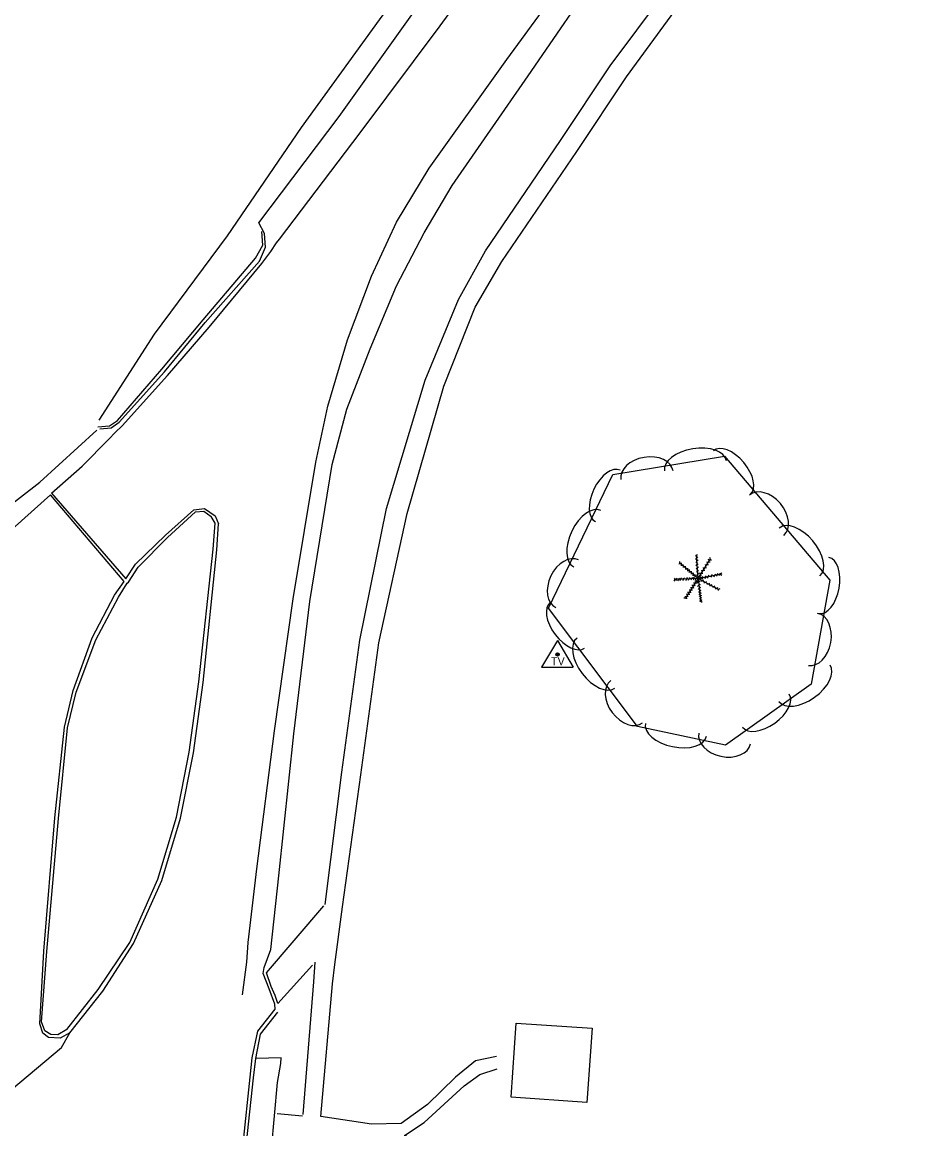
# Model space of a CAD drawing. Extents: x 1042086 to 1119166, y 1916606 to 1927565.
# Drawn here: x 1043276.4 to 1043446.1, y 1926644.3 to 1926851.6 of the extents above; entities that cross this region are included whole.
import ezdxf

# ---------------------------------------------------------------- set-up
doc = ezdxf.new("R2010")
doc.units = 0
for name, color, linetype in [('S_BUILDING', 7, 'Continuous'), ('S_CURB', 7, 'Continuous'), ('S_EDGE_CONCRETE', 7, 'Continuous'), ('S_EDGE_PAVEMENT', 7, 'Continuous'), ('S_GRAVEL_ROAD', 7, 'Continuous'), ('S_SECONDARY_CTL', 7, 'Continuous'), ('S_SHOULDER', 7, 'Continuous'), ('S_SIDEWALK', 7, 'Continuous'), ('S_TREE', 7, 'Continuous')]:
    doc.layers.add(name, color=color, linetype=linetype)

msp = doc.modelspace()

# ---------------------------------------------------------------- linework, layer by layer
at = {"layer": 'S_BUILDING'}
msp.add_lwpolyline([(1043382.17, 1926649.21), (1043367.97, 1926650.21), (1043368.94, 1926664.09), (1043383.15, 1926663.1)], close=True, dxfattribs=at)
at = {"layer": 'S_CURB'}
for points in [[(1043290.59, 1926775.81), (1043292.73, 1926775.98), (1043294.25, 1926776.99), (1043302.57, 1926786.62), (1043310.27, 1926795.81), (1043320.09, 1926807.37), (1043321.47, 1926809.84), (1043321.31, 1926812.39)], [(1043296.32, 1926746.71), (1043298.1, 1926749.51), (1043303.62, 1926755.08), (1043308.84, 1926759.86), (1043310.42, 1926759.98), (1043311.82, 1926759.01)], [(1043284.75, 1926662.87), (1043290.65, 1926670.35), (1043296.54, 1926679.18), (1043301.78, 1926691.03), (1043305.32, 1926702.69), (1043307.65, 1926714.83), (1043309.46, 1926728.01), (1043312.18, 1926752.86), (1043312.55, 1926757.72), (1043311.82, 1926759.01)], [(1043284.75, 1926662.87), (1043283.09, 1926661.87), (1043281.76, 1926661.95), (1043280.61, 1926662.63), (1043279.99, 1926664.31), (1043280.99, 1926677.5), (1043283.18, 1926702.42), (1043284.88, 1926719.42), (1043286.53, 1926726.07), (1043290.21, 1926735.89), (1043294.45, 1926743.85), (1043296.09, 1926746.5), (1043296.32, 1926746.71)], [(1043203.91, 1926532.06), (1043222.97, 1926548.25), (1043242.02, 1926564.43), (1043261.02, 1926580.68), (1043280.9, 1926597.45), (1043299.84, 1926613.77), (1043313.23, 1926625.02), (1043315.83, 1926627.5), (1043317.07, 1926628.88), (1043319.73, 1926653.81), (1043320.19, 1926657.43), (1043321.03, 1926661.98), (1043324.28, 1926666.15)]]:
    msp.add_lwpolyline(points, dxfattribs=at)
at = {"layer": 'S_EDGE_CONCRETE'}
for points in [[(1043333.14, 1926686.28), (1043336.25, 1926711.07), (1043339.64, 1926735.81), (1043344.67, 1926760.46), (1043351.86, 1926784.55), (1043358.12, 1926799.66), (1043363.22, 1926808.77), (1043377.25, 1926829.45), (1043386.53, 1926843.44), (1043401.54, 1926863.54), (1043417.33, 1926882.95), (1043432.92, 1926902.49), (1043449.21, 1926921.54), (1043465.95, 1926940.19), (1043482.96, 1926958.51), (1043500.59, 1926976.22), (1043518.59, 1926993.74), (1043537.15, 1927010.47), (1043556.08, 1927026.84), (1043574.87, 1927043.32), (1043593.74, 1927059.7), (1043596.5, 1927062.22)], [(1043332.36, 1926646.56), (1043334.5, 1926671.41), (1043334.97, 1926675.06), (1043336.37, 1926685.87), (1043339.84, 1926710.61), (1043343.21, 1926735.35), (1043348.53, 1926759.57), (1043355.39, 1926783.41), (1043361.24, 1926798.22), (1043366.25, 1926806.77), (1043380.3, 1926827.37), (1043389.58, 1926841.36), (1043404.26, 1926861.45)], [(1042911.59, 1926420.57), (1042897.9, 1926435.96), (1042900.77, 1926438.95), (1042919.78, 1926455.34), (1042939.53, 1926471.89), (1042958.48, 1926488.19), (1042977.65, 1926504.25), (1042996.58, 1926520.57), (1043015.53, 1926536.87), (1043034.78, 1926552.83), (1043053.68, 1926569.19), (1043072.77, 1926585.33), (1043091.84, 1926601.49), (1043110.9, 1926617.67), (1043129.98, 1926633.83), (1043149.08, 1926649.95), (1043168.09, 1926666.19), (1043187.12, 1926682.4), (1043206.26, 1926698.48), (1043225.26, 1926714.73), (1043244.49, 1926730.7), (1043263.56, 1926746.87), (1043281.72, 1926763.08)], [(1043285.33, 1926662.23), (1043283.52, 1926661.24), (1043281.31, 1926661.4), (1043280.27, 1926662.21), (1043279.69, 1926663.94), (1043280.44, 1926677.57), (1043282.5, 1926702.51), (1043284.34, 1926719.5), (1043285.93, 1926726.4), (1043289.5, 1926736.28), (1043293.67, 1926744.28), (1043295.47, 1926746.84), (1043281.72, 1926763.08)], [(1043322.19, 1926673.51), (1043332.89, 1926686.06)], [(1043324.26, 1926667.74), (1043330.77, 1926674.94)], [(1043329, 1926646.95), (1043331.06, 1926671.81), (1043331.29, 1926675.48)], [(1043324.26, 1926667.74), (1043323.76, 1926669.26), (1043323.01, 1926670.95), (1043322.19, 1926673.51)]]:
    msp.add_lwpolyline(points, dxfattribs=at)
at = {"layer": 'S_EDGE_PAVEMENT'}
for points in [[(1043281.9, 1926763.36), (1043287.65, 1926768.44), (1043292.63, 1926773.46), (1043293.81, 1926774.73), (1043295.14, 1926775.98), (1043303.63, 1926785.39), (1043311.43, 1926794.47), (1043321.3, 1926806.42), (1043322.98, 1926808.66), (1043324.05, 1926810.26), (1043324.6, 1926810.97), (1043339.74, 1926830.85), (1043354.67, 1926850.89), (1043369.38, 1926871.11)], [(1043317.69, 1926669.37), (1043318.5, 1926675.48), (1043318.75, 1926679.21), (1043320.34, 1926692.95), (1043323.65, 1926718.81), (1043327.17, 1926743.54), (1043331.43, 1926769.16), (1043333.67, 1926779.64), (1043337.33, 1926792.07), (1043341.83, 1926803.99), (1043346.54, 1926814.16), (1043352.63, 1926824.28), (1043367.16, 1926844.62), (1043381.91, 1926864.8)], [(1043281.9, 1926763.36), (1043295.8, 1926747.32), (1043297.61, 1926750.09), (1043303.26, 1926755.5), (1043308.53, 1926760.23), (1043310.55, 1926760.49), (1043312.57, 1926759.13), (1043313.2, 1926757.62)], [(1043134.32, 1926532.4), (1043153.39, 1926548.56), (1043172.45, 1926564.73), (1043191.46, 1926580.98), (1043217.47, 1926603.49), (1043236.61, 1926619.59), (1043264.57, 1926643.47), (1043283.75, 1926659.52), (1043285.33, 1926662.23), (1043291.48, 1926670.09), (1043297.24, 1926678.97), (1043302.57, 1926690.78), (1043306.08, 1926702.45), (1043308.51, 1926714.7), (1043310.31, 1926727.88), (1043312.83, 1926752.76), (1043313.2, 1926757.62)], [(1043323.75, 1926667.62), (1043322.68, 1926670.49), (1043321.54, 1926673.35)], [(1043203.53, 1926532.51), (1043222.69, 1926548.57), (1043241.6, 1926564.93), (1043260.67, 1926581.1), (1043280.46, 1926597.97), (1043299.5, 1926614.17), (1043312.64, 1926625.13), (1043315.29, 1926627.6), (1043316.5, 1926628.99), (1043319.12, 1926653.92), (1043319.48, 1926657.56), (1043320.51, 1926662.56), (1043323.81, 1926666.68), (1043323.75, 1926667.62)]]:
    msp.add_lwpolyline(points, dxfattribs=at)
at = {"layer": 'S_GRAVEL_ROAD'}
msp.add_lwpolyline([(1043290.8, 1926777.06), (1043301.17, 1926793.14), (1043314.84, 1926811.56), (1043328.75, 1926831.89), (1043343.36, 1926852.02), (1043358.14, 1926872.22), (1043373.09, 1926892.3), (1043388.7, 1926911.95), (1043404.64, 1926931.31), (1043421.11, 1926950.25), (1043438.08, 1926968.8), (1043455.2, 1926986.98), (1043472.44, 1927005.37), (1043490.55, 1927022.67), (1043508.78, 1927039.76), (1043527.06, 1927056.75), (1043545.79, 1927073.47), (1043564.81, 1927089.53), (1043575.98, 1927099.12)], dxfattribs=at)
at = {"layer": 'S_SECONDARY_CTL'}
for p, q in [((1043376.68, 1926735.75), (1043373.67, 1926730.79)), ((1043376.68, 1926735.75), (1043379.62, 1926730.79)), ((1043373.67, 1926730.79), (1043379.62, 1926730.79))]:
    msp.add_line(p, q, dxfattribs=at)
for radius in [0.311, 0.183, 0.103]:
    msp.add_circle((1043376.68, 1926733.14), radius, dxfattribs=at)
at = {"layer": 'S_SHOULDER'}
for points in [[(1043321.54, 1926673.35), (1043321.72, 1926674.47), (1043322.96, 1926677.89), (1043324.48, 1926691.65), (1043327.26, 1926718.27), (1043330.25, 1926743.08), (1043334.45, 1926768.71), (1043337.21, 1926779.12), (1043341.58, 1926790.42), (1043346.49, 1926802.18), (1043351.73, 1926812.14), (1043356.93, 1926821.01), (1043371.17, 1926841.58), (1043385.33, 1926862.2)], [(1043290.93, 1926775.42), (1043293.07, 1926775.59), (1043294.56, 1926776.64), (1043303.03, 1926786.08), (1043310.7, 1926795.31), (1043320.82, 1926806.8), (1043322, 1926809.43), (1043321.79, 1926812.01), (1043320.71, 1926814), (1043335.75, 1926833.96), (1043350.33, 1926854.27)], [(1042898.35, 1926441.3), (1042916.65, 1926458.38), (1042936.71, 1926475.14), (1042955.64, 1926491.46), (1042974.65, 1926507.71), (1042994.08, 1926523.45), (1043013.1, 1926539.67), (1043032.23, 1926555.77), (1043051, 1926572.28), (1043069.8, 1926588.75), (1043089.02, 1926604.75), (1043107.89, 1926621.14), (1043127.31, 1926636.9), (1043146.59, 1926652.82), (1043165.47, 1926669.21), (1043184.66, 1926685.24), (1043203.58, 1926701.57), (1043222.63, 1926717.76), (1043241.64, 1926733.98), (1043260.43, 1926750.48), (1043279.67, 1926765.43), (1043290.38, 1926775.16)]]:
    msp.add_lwpolyline(points, dxfattribs=at)
at = {"layer": 'S_SIDEWALK'}
for points in [[(1043206.87, 1926528.51), (1043225.94, 1926544.68), (1043244.93, 1926560.94), (1043263.92, 1926577.21), (1043283.82, 1926593.93), (1043302.81, 1926610.2), (1043318.87, 1926623.94), (1043321.48, 1926626.42), (1043321.95, 1926627.95), (1043324.25, 1926652.94), (1043324.82, 1926656.54), (1043324.91, 1926657.57), (1043320.19, 1926657.43)], [(1043365.23, 1926657.84), (1043361.33, 1926657.01), (1043357.57, 1926653.97), (1043352.34, 1926648.85), (1043347.4, 1926645.28), (1043341.83, 1926645.13), (1043332.36, 1926646.56)], [(1043378.51, 1926624.1), (1043363.94, 1926634.31), (1043354.84, 1926640.12), (1043348.01, 1926643), (1043351.69, 1926645.43), (1043359.2, 1926652.3), (1043362.12, 1926654.46), (1043365.35, 1926655.49)], [(1043328.91, 1926646.65), (1043324.18, 1926647.06)]]:
    msp.add_lwpolyline(points, dxfattribs=at)
at = {"layer": 'S_TREE'}
for p, q in [((1043402.75, 1926751.46), (1043402.52, 1926751.66)), ((1043403, 1926747.38), (1043402.74, 1926751.82)), ((1043402.75, 1926751.71), (1043402.93, 1926751.94)), ((1043402.78, 1926751.23), (1043402.96, 1926751.46)), ((1043399.72, 1926750.12), (1043399.42, 1926750.08)), ((1043403, 1926747.38), (1043399.54, 1926750.29)), ((1043399.58, 1926750.26), (1043399.58, 1926750.56)), ((1043400.07, 1926749.84), (1043399.77, 1926749.82)), ((1043399.89, 1926750.01), (1043399.89, 1926750.31)), ((1043400.43, 1926749.52), (1043400.13, 1926749.5)), ((1043400.25, 1926749.72), (1043400.25, 1926750.02)), ((1043400.66, 1926749.36), (1043400.66, 1926749.66)), ((1043402.78, 1926750.9), (1043402.56, 1926751.09)), ((1043402.81, 1926750.32), (1043402.59, 1926750.52)), ((1043402.84, 1926749.66), (1043402.61, 1926749.86)), ((1043402.81, 1926750.63), (1043403, 1926750.86)), ((1043402.85, 1926749.92), (1043403.03, 1926750.15)), ((1043402.91, 1926749.35), (1043403.1, 1926749.59)), ((1043403, 1926747.38), (1043405.35, 1926751.06)), ((1043404.11, 1926749.15), (1043404.02, 1926749.44)), ((1043404.32, 1926749.39), (1043404.62, 1926749.44)), ((1043404.48, 1926749.72), (1043404.39, 1926750.01)), ((1043404.64, 1926749.93), (1043404.94, 1926749.98)), ((1043404.78, 1926750.24), (1043404.69, 1926750.52)), ((1043404.97, 1926750.42), (1043405.26, 1926750.47)), ((1043405.08, 1926750.69), (1043404.99, 1926750.98)), ((1043405.21, 1926750.85), (1043405.51, 1926750.89)), ((1043405.32, 1926751.03), (1043405.23, 1926751.32)), ((1043403, 1926747.38), (1043398.55, 1926747.17)), ((1043398.79, 1926747.19), (1043398.62, 1926747.44)), ((1043399.17, 1926747.22), (1043399, 1926747.46)), ((1043399.57, 1926747.22), (1043399.4, 1926747.46)), ((1043399.97, 1926747.24), (1043399.8, 1926747.49)), ((1043400.54, 1926747.25), (1043400.37, 1926747.5)), ((1043400.89, 1926749.15), (1043400.59, 1926749.12)), ((1043403, 1926747.38), (1043400.62, 1926743.61)), ((1043401.09, 1926747.29), (1043400.93, 1926747.54)), ((1043401.25, 1926748.82), (1043400.95, 1926748.79)), ((1043401.08, 1926749.03), (1043401.08, 1926749.33)), ((1043401.58, 1926748.55), (1043401.29, 1926748.53)), ((1043401.4, 1926748.75), (1043401.4, 1926749.05)), ((1043401.57, 1926747.31), (1043401.4, 1926747.55)), ((1043401.93, 1926748.26), (1043401.63, 1926748.23)), ((1043401.77, 1926747.32), (1043401.64, 1926747.05)), ((1043401.77, 1926748.44), (1043401.77, 1926748.74)), ((1043402.01, 1926747.35), (1043401.84, 1926747.59)), ((1043402.29, 1926747.96), (1043402, 1926747.94)), ((1043402.23, 1926747.33), (1043402.1, 1926747.06)), ((1043402.13, 1926748.14), (1043402.13, 1926748.44)), ((1043402.35, 1926747.38), (1043402.18, 1926747.63)), ((1043402.66, 1926747.66), (1043402.36, 1926747.64)), ((1043402.62, 1926747.34), (1043402.48, 1926747.07)), ((1043402.49, 1926747.82), (1043402.49, 1926748.12)), ((1043402.88, 1926749.07), (1043402.65, 1926749.27)), ((1043402.91, 1926748.5), (1043402.69, 1926748.7)), ((1043402.93, 1926747.88), (1043402.7, 1926748.08)), ((1043402.92, 1926748.78), (1043403.11, 1926749.02)), ((1043402.95, 1926748.11), (1043403.14, 1926748.35)), ((1043403, 1926747.38), (1043407.42, 1926748.25)), ((1043403, 1926747.38), (1043406.92, 1926745.33)), ((1043403, 1926747.38), (1043403.54, 1926743.01)), ((1043403.33, 1926747.2), (1043403.6, 1926747.34)), ((1043403.35, 1926747.87), (1043403.65, 1926747.91)), ((1043403.45, 1926748.13), (1043403.36, 1926748.42)), ((1043403.38, 1926747.46), (1043403.58, 1926747.69)), ((1043403.62, 1926747.5), (1043403.88, 1926747.34)), ((1043403.64, 1926748.33), (1043403.93, 1926748.38)), ((1043403.81, 1926748.66), (1043403.72, 1926748.95)), ((1043403.78, 1926747.52), (1043403.98, 1926747.74)), ((1043403.97, 1926748.88), (1043404.27, 1926748.92)), ((1043404.14, 1926747.57), (1043404.39, 1926747.41)), ((1043404.31, 1926747.63), (1043404.51, 1926747.85)), ((1043404.66, 1926747.69), (1043404.91, 1926747.53)), ((1043404.88, 1926747.75), (1043405.08, 1926747.98)), ((1043405.26, 1926747.82), (1043405.52, 1926747.66)), ((1043405.51, 1926747.9), (1043405.71, 1926748.12)), ((1043405.84, 1926747.92), (1043406.1, 1926747.76)), ((1043406.1, 1926747.99), (1043406.31, 1926748.21)), ((1043406.35, 1926748.04), (1043406.61, 1926747.88)), ((1043406.59, 1926748.09), (1043406.79, 1926748.31)), ((1043406.78, 1926748.13), (1043407.03, 1926747.97)), ((1043407.03, 1926748.18), (1043407.23, 1926748.4)), ((1043407.18, 1926748.19), (1043407.44, 1926748.03)), ((1043407.26, 1926748.23), (1043407.46, 1926748.45)), ((1043398.64, 1926747.17), (1043398.5, 1926746.9)), ((1043398.98, 1926747.19), (1043398.85, 1926746.92)), ((1043399.33, 1926747.21), (1043399.19, 1926746.94)), ((1043399.75, 1926747.22), (1043399.61, 1926746.96)), ((1043400.26, 1926747.25), (1043400.12, 1926746.98)), ((1043400.82, 1926747.28), (1043400.68, 1926747.01)), ((1043401.3, 1926747.3), (1043401.17, 1926747.03)), ((1043401.91, 1926745.65), (1043401.61, 1926745.62)), ((1043401.79, 1926745.44), (1043401.87, 1926745.15)), ((1043402.16, 1926746.07), (1043401.86, 1926746.04)), ((1043402.05, 1926745.87), (1043402.13, 1926745.58)), ((1043402.44, 1926746.52), (1043402.14, 1926746.48)), ((1043402.31, 1926746.28), (1043402.38, 1926745.99)), ((1043402.68, 1926746.88), (1043402.38, 1926746.85)), ((1043402.58, 1926746.72), (1043402.66, 1926746.43)), ((1043402.8, 1926747.06), (1043402.87, 1926746.77)), ((1043403.07, 1926746.7), (1043402.87, 1926746.48)), ((1043403.13, 1926746.12), (1043402.93, 1926745.9)), ((1043403.21, 1926745.56), (1043403.02, 1926745.33)), ((1043403.08, 1926746.95), (1043403.34, 1926746.8)), ((1043403.12, 1926746.4), (1043403.38, 1926746.24)), ((1043403.2, 1926745.83), (1043403.46, 1926745.68)), ((1043403.27, 1926745.28), (1043403.52, 1926745.13)), ((1043403.51, 1926747.1), (1043403.58, 1926746.81)), ((1043403.81, 1926746.97), (1043404.08, 1926747.11)), ((1043404.09, 1926746.8), (1043404.17, 1926746.51)), ((1043404.37, 1926746.67), (1043404.63, 1926746.81)), ((1043404.63, 1926746.52), (1043404.7, 1926746.23)), ((1043404.92, 1926746.39), (1043405.19, 1926746.53)), ((1043405.15, 1926746.25), (1043405.22, 1926745.96)), ((1043405.4, 1926746.13), (1043405.67, 1926746.27)), ((1043405.69, 1926745.95), (1043405.76, 1926745.66)), ((1043405.94, 1926745.86), (1043406.21, 1926746)), ((1043406.2, 1926745.7), (1043406.28, 1926745.4)), ((1043406.49, 1926745.58), (1043406.75, 1926745.72)), ((1043406.69, 1926745.44), (1043406.77, 1926745.15)), ((1043406.88, 1926745.37), (1043407.15, 1926745.51)), ((1043400.66, 1926743.69), (1043400.36, 1926743.66)), ((1043400.86, 1926743.99), (1043400.56, 1926743.96)), ((1043400.78, 1926743.85), (1043400.85, 1926743.56)), ((1043401.11, 1926744.41), (1043400.81, 1926744.37)), ((1043401, 1926744.2), (1043401.08, 1926743.91)), ((1043401.35, 1926744.78), (1043401.05, 1926744.75)), ((1043401.26, 1926744.6), (1043401.34, 1926744.31)), ((1043401.64, 1926745.23), (1043401.34, 1926745.2)), ((1043401.51, 1926744.98), (1043401.58, 1926744.69)), ((1043403.29, 1926744.99), (1043403.09, 1926744.77)), ((1043403.35, 1926744.54), (1043403.15, 1926744.31)), ((1043403.39, 1926744.16), (1043403.19, 1926743.93)), ((1043403.45, 1926743.71), (1043403.25, 1926743.48)), ((1043403.49, 1926743.29), (1043403.3, 1926743.06)), ((1043403.34, 1926744.77), (1043403.6, 1926744.62)), ((1043403.37, 1926744.34), (1043403.63, 1926744.18)), ((1043403.42, 1926743.93), (1043403.67, 1926743.78)), ((1043403.48, 1926743.47), (1043403.74, 1926743.31)), ((1043403.52, 1926743.13), (1043403.78, 1926742.97))]:
    msp.add_line(p, q, dxfattribs=at)
msp.add_lwpolyline([(1043391.69, 1926719.63), (1043375.02, 1926741.8), (1043387.02, 1926766.83), (1043407.96, 1926770.29), (1043427.68, 1926747.09), (1043424.22, 1926727.56), (1043408.16, 1926716.17)], close=True, dxfattribs=at)
for centre, major_axis, ratio in [((1043402.53, 1926768.48), (-5.79, -0.96), 0.55008), ((1043409.36, 1926767.25), (-3.46, 4.07), 0.540699), ((1043393.44, 1926766.72), (-4.89, -0.81), 0.685311), ((1043386.1, 1926762.85), (-2.31, -4.82), 0.540699), ((1043415.84, 1926759.23), (-3.21, 3.77), 0.685311), ((1043382.27, 1926754.85), (-2.54, -5.29), 0.55008), ((1043422.03, 1926752.35), (-3.8, 4.47), 0.55008), ((1043378.5, 1926746.39), (-2.14, -4.47), 0.685311), ((1043426.58, 1926746.06), (0.93, 5.26), 0.540699), ((1043378.54, 1926738.62), (3.21, -4.27), 0.540699), ((1043424.53, 1926735.96), (0.86, 4.88), 0.685311), ((1043383.87, 1926731.53), (3.53, -4.69), 0.55008), ((1043422.94, 1926727.75), (4.79, 3.4), 0.55008), ((1043389.64, 1926724.29), (2.98, -3.96), 0.685311), ((1043415.71, 1926722.62), (4.36, 3.09), 0.540699), ((1043398.88, 1926719.03), (5.74, -1.21), 0.55008), ((1043407.99, 1926717.39), (4.85, -1.02), 0.685311)]:
    msp.add_ellipse(centre, major_axis=major_axis, ratio=ratio, start_param=3.141593, end_param=6.283185, dxfattribs=at)

# ---------------------------------------------------------------- texts
at = {"layer": 'S_SECONDARY_CTL'}
msp.add_text('TV', height=1.5, rotation=360, dxfattribs=at).set_placement((1043375.47, 1926731.13))

doc.saveas('drawing.dxf')
